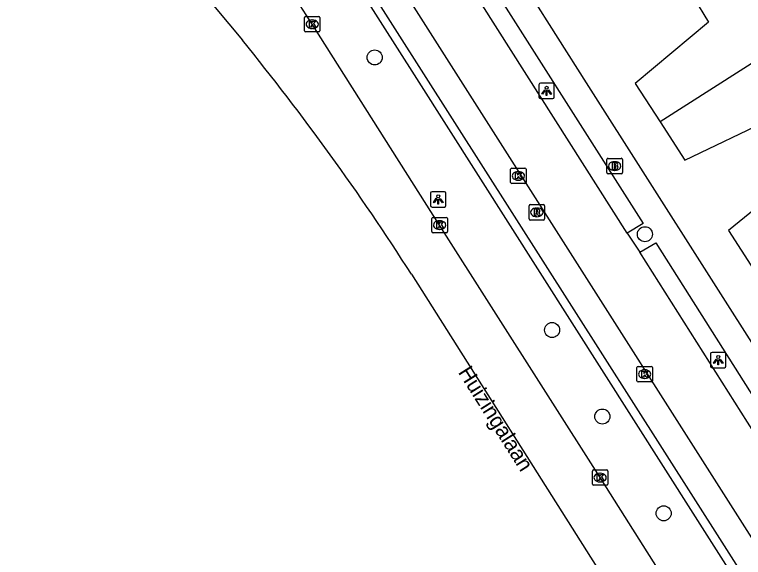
# Model space of a CAD drawing. Extents: x 159689 to 160786, y 387323 to 388339.
# Drawn here: x 159843.32 to 159890.67, y 387635.68 to 387670.93 of the extents above; entities that cross this region are included whole.
import ezdxf

# ---------------------------------------------------------------- set-up
doc = ezdxf.new("R2010")
doc.units = 0
for name, color, linetype in [('IMGEO_Boom', 7, 'Continuous'), ('IMGEO_Brandkraan', 7, 'Continuous'), ('IMGEO_Fietspad_gesloten', 7, 'Continuous'), ('IMGEO_Kolk', 7, 'Continuous'), ('IMGEO_Lichtpunt', 7, 'Continuous'), ('IMGEO_Openbare_ruimte_label', 7, 'Continuous'), ('IMGEO_OVBaan_gesloten', 7, 'Continuous'), ('IMGEO_Pand', 7, 'Continuous'), ('IMGEO_Rijbaan_regionaal_gesloten', 7, 'Continuous'), ('IMGEO_Rioolput', 7, 'Continuous'), ('IMGEO_Voetpad_open', 7, 'Continuous')]:
    doc.layers.add(name, color=color, linetype=linetype)

msp = doc.modelspace()

# ---------------------------------------------------------------- linework, layer by layer
at = {"layer": 'IMGEO_Boom'}
for centre in [(159866.716, 387668.144), (159884.273, 387656.663), (159878.24, 387650.442), (159881.507, 387644.824), (159885.49, 387638.542)]:
    msp.add_circle(centre, 0.489, dxfattribs=at)
at = {"layer": 'IMGEO_Brandkraan'}
for p, q in [((159881.807, 387660.665), (159881.807, 387661.517)), ((159881.882, 387661.591), (159882.734, 387661.591)), ((159882.295, 387661.371), (159882.32, 387661.371)), ((159882.808, 387661.517), (159882.808, 387660.665)), ((159882.734, 387660.591), (159881.882, 387660.591)), ((159882.318, 387660.811), (159882.293, 387660.811))]:
    msp.add_line(p, q, dxfattribs=at)
for points in [[(159881.807, 387660.665), (159881.807, 387661.517)], [(159881.882, 387661.591), (159882.734, 387661.591)], [(159882.808, 387661.517), (159882.808, 387660.665)], [(159882.155, 387661.291), (159882.155, 387660.891), (159882.368, 387660.891)], [(159882.386, 387661.291), (159882.155, 387661.291)], [(159882.334, 387661.21), (159882.28, 387661.21), (159882.28, 387661.134)], [(159882.28, 387661.134), (159882.333, 387661.134)], [(159882.342, 387661.058), (159882.28, 387661.058), (159882.28, 387660.977)], [(159882.28, 387660.977), (159882.342, 387660.977)], [(159882.734, 387660.591), (159881.882, 387660.591)]]:
    msp.add_lwpolyline(points, dxfattribs=at)
for centre, radius, start, end in [((159881.884, 387661.515), 0.0765, 91.552, 178.448), ((159881.884, 387661.515), 0.0765, 91.552, 178.448), ((159882.732, 387661.515), 0.0765, 1.552, 88.448), ((159882.732, 387661.515), 0.0765, 1.552, 88.448), ((159882.335, 387661.172), 0.0379, 267.8285, 90.9355), ((159882.343, 387661.017), 0.0404, 269.8759, 90.5077), ((159882.374, 387661.142), 0.251, 268.6676, 293.5347), ((159882.39, 387661.146), 0.145, 59.4692, 91.5367), ((159882.415, 387661.193), 0.0922, 285.5137, 58.1501), ((159882.42, 387661.001), 0.105, 301.3115, 78.989), ((159881.884, 387660.667), 0.0765, 181.552, 268.448), ((159881.884, 387660.667), 0.0765, 181.552, 268.448), ((159882.732, 387660.667), 0.0765, 271.552, 358.448), ((159882.732, 387660.667), 0.0765, 271.552, 358.448)]:
    msp.add_arc(centre, radius, start, end, dxfattribs=at)
for centre, major_axis, ratio, start_param, end_param in [((159882.294, 387661.091), (-0.387, 0.002), 0.722429, 4.712389, 7.853982), ((159882.319, 387661.091), (-0.39, 0.002), 0.717154, 1.570796, 4.712389)]:
    msp.add_ellipse(centre, major_axis=major_axis, ratio=ratio, start_param=start_param, end_param=end_param, dxfattribs=at)
at = {"layer": 'IMGEO_Fietspad_gesloten'}
for points in [[(159858.565, 387688.232), (159871.375, 387668.071), (159896.663, 387628.381), (159918.222, 387594.432), (159932.893, 387571.356)], [(159883.122, 387656.732), (159871.809, 387674.544)], [(159883.122, 387656.732), (159883.934, 387655.5)], [(159895.454, 387637.315), (159883.934, 387655.5)]]:
    msp.add_lwpolyline(points, dxfattribs=at)
at = {"layer": 'IMGEO_Kolk'}
for p, q in [((159862.23, 387670.801), (159863.082, 387670.801)), ((159862.155, 387669.875), (159862.155, 387670.727)), ((159862.643, 387670.581), (159862.668, 387670.581)), ((159863.156, 387670.727), (159863.156, 387669.875)), ((159862.666, 387670.021), (159862.641, 387670.021)), ((159863.082, 387669.801), (159862.23, 387669.801)), ((159875.549, 387660.026), (159875.549, 387660.878)), ((159875.624, 387660.952), (159876.476, 387660.952)), ((159876.55, 387660.878), (159876.55, 387660.026)), ((159876.037, 387660.732), (159876.062, 387660.732)), ((159876.476, 387659.952), (159875.624, 387659.952)), ((159876.06, 387660.172), (159876.035, 387660.172)), ((159870.435, 387656.833), (159870.435, 387657.685)), ((159870.51, 387657.759), (159871.362, 387657.759)), ((159870.923, 387657.539), (159870.948, 387657.539)), ((159871.436, 387657.685), (159871.436, 387656.833)), ((159871.362, 387656.759), (159870.51, 387656.759)), ((159870.946, 387656.979), (159870.921, 387656.979)), ((159883.83, 387648.078), (159884.682, 387648.078)), ((159883.755, 387647.152), (159883.755, 387648.004)), ((159884.243, 387647.858), (159884.268, 387647.858)), ((159884.756, 387648.004), (159884.756, 387647.152)), ((159884.266, 387647.298), (159884.241, 387647.298)), ((159884.682, 387647.078), (159883.83, 387647.078)), ((159880.857, 387640.436), (159880.857, 387641.288)), ((159880.932, 387641.362), (159881.784, 387641.362)), ((159881.345, 387641.142), (159881.37, 387641.142)), ((159881.858, 387641.288), (159881.858, 387640.436)), ((159881.368, 387640.582), (159881.343, 387640.582)), ((159881.784, 387640.362), (159880.932, 387640.362))]:
    msp.add_line(p, q, dxfattribs=at)
for points in [[(159862.23, 387670.801), (159863.082, 387670.801)], [(159862.155, 387669.875), (159862.155, 387670.727)], [(159862.476, 387670.501), (159862.599, 387670.501), (159862.599, 387670.35), (159862.729, 387670.501), (159862.893, 387670.501), (159862.747, 387670.35), (159862.9, 387670.101), (159862.748, 387670.101), (159862.663, 387670.265), (159862.599, 387670.198), (159862.599, 387670.101), (159862.476, 387670.101), (159862.476, 387670.501)], [(159863.156, 387670.727), (159863.156, 387669.875)], [(159863.082, 387669.801), (159862.23, 387669.801)], [(159875.549, 387660.026), (159875.549, 387660.878)], [(159875.624, 387660.952), (159876.476, 387660.952)], [(159876.55, 387660.878), (159876.55, 387660.026)], [(159875.87, 387660.652), (159875.993, 387660.652), (159875.993, 387660.501), (159876.123, 387660.652), (159876.287, 387660.652), (159876.141, 387660.501), (159876.294, 387660.252), (159876.142, 387660.252), (159876.057, 387660.416), (159875.993, 387660.349), (159875.993, 387660.252), (159875.87, 387660.252), (159875.87, 387660.652)], [(159876.476, 387659.952), (159875.624, 387659.952)], [(159870.435, 387656.833), (159870.435, 387657.685)], [(159870.51, 387657.759), (159871.362, 387657.759)], [(159871.436, 387657.685), (159871.436, 387656.833)], [(159870.756, 387657.459), (159870.879, 387657.459), (159870.879, 387657.308), (159871.009, 387657.459), (159871.173, 387657.459), (159871.027, 387657.308), (159871.18, 387657.059), (159871.028, 387657.059), (159870.943, 387657.223), (159870.879, 387657.156), (159870.879, 387657.059), (159870.756, 387657.059), (159870.756, 387657.459)], [(159871.362, 387656.759), (159870.51, 387656.759)], [(159883.83, 387648.078), (159884.682, 387648.078)], [(159883.755, 387647.152), (159883.755, 387648.004)], [(159884.076, 387647.778), (159884.199, 387647.778), (159884.199, 387647.627), (159884.329, 387647.778), (159884.493, 387647.778), (159884.347, 387647.627), (159884.5, 387647.378), (159884.348, 387647.378), (159884.263, 387647.542), (159884.199, 387647.475), (159884.199, 387647.378), (159884.076, 387647.378), (159884.076, 387647.778)], [(159884.756, 387648.004), (159884.756, 387647.152)], [(159884.682, 387647.078), (159883.83, 387647.078)], [(159880.857, 387640.436), (159880.857, 387641.288)], [(159880.932, 387641.362), (159881.784, 387641.362)], [(159881.178, 387641.062), (159881.301, 387641.062), (159881.301, 387640.911), (159881.431, 387641.062), (159881.595, 387641.062), (159881.449, 387640.911), (159881.602, 387640.662), (159881.45, 387640.662), (159881.365, 387640.826), (159881.301, 387640.759), (159881.301, 387640.662), (159881.178, 387640.662), (159881.178, 387641.062)], [(159881.858, 387641.288), (159881.858, 387640.436)], [(159881.784, 387640.362), (159880.932, 387640.362)]]:
    msp.add_lwpolyline(points, dxfattribs=at)
for centre, start, end in [((159862.232, 387670.725), 91.552, 178.448), ((159862.232, 387670.725), 91.552, 178.448), ((159863.08, 387670.725), 1.552, 88.448), ((159863.08, 387670.725), 1.552, 88.448), ((159862.232, 387669.877), 181.552, 268.448), ((159862.232, 387669.877), 181.552, 268.448), ((159863.08, 387669.877), 271.552, 358.448), ((159863.08, 387669.877), 271.552, 358.448), ((159875.626, 387660.876), 91.552, 178.448), ((159875.626, 387660.876), 91.552, 178.448), ((159876.474, 387660.876), 1.552, 88.448), ((159876.474, 387660.876), 1.552, 88.448), ((159875.626, 387660.028), 181.552, 268.448), ((159875.626, 387660.028), 181.552, 268.448), ((159876.474, 387660.028), 271.552, 358.448), ((159876.474, 387660.028), 271.552, 358.448), ((159870.512, 387657.683), 91.552, 178.448), ((159870.512, 387657.683), 91.552, 178.448), ((159871.36, 387657.683), 1.552, 88.448), ((159871.36, 387657.683), 1.552, 88.448), ((159870.512, 387656.835), 181.552, 268.448), ((159870.512, 387656.835), 181.552, 268.448), ((159871.36, 387656.835), 271.552, 358.448), ((159871.36, 387656.835), 271.552, 358.448), ((159883.832, 387648.002), 91.552, 178.448), ((159883.832, 387648.002), 91.552, 178.448), ((159884.68, 387648.002), 1.552, 88.448), ((159884.68, 387648.002), 1.552, 88.448), ((159883.832, 387647.154), 181.552, 268.448), ((159883.832, 387647.154), 181.552, 268.448), ((159884.68, 387647.154), 271.552, 358.448), ((159884.68, 387647.154), 271.552, 358.448), ((159880.934, 387641.286), 91.552, 178.448), ((159880.934, 387641.286), 91.552, 178.448), ((159881.782, 387641.286), 1.552, 88.448), ((159881.782, 387641.286), 1.552, 88.448), ((159880.934, 387640.438), 181.552, 268.448), ((159880.934, 387640.438), 181.552, 268.448), ((159881.782, 387640.438), 271.552, 358.448), ((159881.782, 387640.438), 271.552, 358.448)]:
    msp.add_arc(centre, 0.0765, start, end, dxfattribs=at)
for centre, major_axis, ratio, start_param, end_param in [((159862.642, 387670.301), (-0.387, 0.002), 0.722429, 4.712389, 7.853982), ((159862.667, 387670.301), (-0.39, 0.002), 0.717154, 1.570796, 4.712389), ((159876.036, 387660.452), (-0.387, 0.002), 0.722429, 4.712389, 7.853982), ((159876.061, 387660.452), (-0.39, 0.002), 0.717154, 1.570796, 4.712389), ((159870.922, 387657.259), (-0.387, 0.002), 0.722429, 4.712389, 7.853982), ((159870.947, 387657.259), (-0.39, 0.002), 0.717154, 1.570796, 4.712389), ((159884.242, 387647.578), (-0.387, 0.002), 0.722429, 4.712389, 7.853982), ((159884.267, 387647.578), (-0.39, 0.002), 0.717154, 1.570796, 4.712389), ((159881.344, 387640.862), (-0.387, 0.002), 0.722429, 4.712389, 7.853982), ((159881.369, 387640.862), (-0.39, 0.002), 0.717154, 1.570796, 4.712389)]:
    msp.add_ellipse(centre, major_axis=major_axis, ratio=ratio, start_param=start_param, end_param=end_param, dxfattribs=at)
at = {"layer": 'IMGEO_Lichtpunt'}
for p, q in [((159877.386, 387666.373), (159877.386, 387665.566)), ((159877.386, 387666.373), (159877.386, 387665.566)), ((159878.288, 387666.468), (159877.48, 387666.468)), ((159878.288, 387666.468), (159877.48, 387666.468)), ((159878.382, 387665.566), (159878.382, 387666.373)), ((159878.382, 387665.566), (159878.382, 387666.373)), ((159877.48, 387665.472), (159878.288, 387665.472)), ((159877.48, 387665.472), (159878.288, 387665.472)), ((159870.346, 387659.33), (159870.346, 387658.523)), ((159870.346, 387659.33), (159870.346, 387658.523)), ((159871.248, 387659.425), (159870.44, 387659.425)), ((159871.248, 387659.425), (159870.44, 387659.425)), ((159871.342, 387658.523), (159871.342, 387659.33)), ((159871.342, 387658.523), (159871.342, 387659.33)), ((159870.44, 387658.429), (159871.248, 387658.429)), ((159870.44, 387658.429), (159871.248, 387658.429)), ((159888.536, 387648.897), (159888.536, 387648.09)), ((159888.536, 387648.897), (159888.536, 387648.09)), ((159889.438, 387648.992), (159888.63, 387648.992)), ((159889.438, 387648.992), (159888.63, 387648.992)), ((159889.532, 387648.09), (159889.532, 387648.897)), ((159889.532, 387648.09), (159889.532, 387648.897)), ((159888.63, 387647.996), (159889.438, 387647.996)), ((159888.63, 387647.996), (159889.438, 387647.996))]:
    msp.add_line(p, q, dxfattribs=at)
for points in [[(159877.76, 387666.037), (159877.799, 387666.009), (159877.611, 387665.747), (159877.573, 387665.774), (159877.76, 387666.037)], [(159877.862, 387665.989), (159877.909, 387665.989), (159877.909, 387665.667), (159877.862, 387665.667), (159877.862, 387665.989)], [(159877.972, 387666.009), (159878.01, 387666.036), (159878.197, 387665.774), (159878.158, 387665.746), (159877.972, 387666.009)], [(159870.72, 387658.994), (159870.759, 387658.966), (159870.571, 387658.704), (159870.533, 387658.731), (159870.72, 387658.994)], [(159870.932, 387658.966), (159870.97, 387658.993), (159871.157, 387658.731), (159871.118, 387658.703), (159870.932, 387658.966)], [(159870.822, 387658.946), (159870.869, 387658.946), (159870.869, 387658.624), (159870.822, 387658.624), (159870.822, 387658.946)], [(159888.91, 387648.561), (159888.949, 387648.533), (159888.761, 387648.271), (159888.723, 387648.298), (159888.91, 387648.561)], [(159889.122, 387648.533), (159889.16, 387648.56), (159889.347, 387648.298), (159889.308, 387648.27), (159889.122, 387648.533)], [(159889.012, 387648.513), (159889.059, 387648.513), (159889.059, 387648.191), (159889.012, 387648.191), (159889.012, 387648.513)]]:
    msp.add_lwpolyline(points, dxfattribs=at)
for centre in [(159877.885, 387666.171), (159870.845, 387659.128), (159889.035, 387648.695)]:
    msp.add_circle(centre, 0.0994, dxfattribs=at)
for centre, start, end in [((159877.48, 387666.373), 90, 180), ((159877.48, 387666.373), 90, 180), ((159878.288, 387666.373), 0, 90), ((159878.288, 387666.373), 0, 90), ((159877.48, 387665.566), 180, 270), ((159877.48, 387665.566), 180, 270), ((159878.288, 387665.566), 270, 0), ((159878.288, 387665.566), 270, 360), ((159870.44, 387659.33), 90, 180), ((159870.44, 387659.33), 90, 180), ((159871.248, 387659.33), 0, 90), ((159871.248, 387659.33), 0, 90), ((159870.44, 387658.523), 180, 270), ((159870.44, 387658.523), 180, 270), ((159871.248, 387658.523), 270, 0), ((159871.248, 387658.523), 270, 360), ((159888.63, 387648.897), 90, 180), ((159888.63, 387648.897), 90, 180), ((159889.438, 387648.897), 0, 90), ((159889.438, 387648.897), 0, 90), ((159888.63, 387648.09), 180, 270), ((159888.63, 387648.09), 180, 270), ((159889.438, 387648.09), 270, 0), ((159889.438, 387648.09), 270, 360)]:
    msp.add_arc(centre, 0.0946, start, end, dxfattribs=at)
at = {"layer": 'IMGEO_OVBaan_gesloten'}
for points in [[(159855.36, 387672.605), (159858.121, 387669.257)], [(159869.099, 387654.066), (159900.012, 387605.234)]]:
    msp.add_lwpolyline(points, dxfattribs=at)
msp.add_arc((159732.596, 387566.983), 161.915, 32.53631, 39.17231, dxfattribs=at)
at = {"layer": 'IMGEO_Pand'}
for points in [[(159900.864, 387673.918), (159885.255, 387663.953)], [(159887.426, 387672.056), (159888.398, 387670.432), (159883.636, 387666.456), (159885.255, 387663.953)], [(159885.255, 387663.953), (159886.863, 387661.467), (159892.467, 387664.154), (159893.533, 387662.473)], [(159893.533, 387662.473), (159894.563, 387660.849), (159889.712, 387656.9), (159891.343, 387654.352)]]:
    msp.add_lwpolyline(points, dxfattribs=at)
at = {"layer": 'IMGEO_Rijbaan_regionaal_gesloten'}
msp.add_lwpolyline([(159895.607, 387618.335), (159893.876, 387621.079), (159881.358, 387640.862), (159870.936, 387657.259), (159862.656, 387670.301), (159859.345, 387675.48), (159854.91, 387682.508), (159848.808, 387692.139), (159844.283, 387699.312), (159843.801, 387700.086), (159843.321, 387700.86)], dxfattribs=at)
at = {"layer": 'IMGEO_Rioolput'}
for p, q in [((159876.749, 387657.657), (159876.749, 387658.509)), ((159876.824, 387658.583), (159877.676, 387658.583)), ((159877.75, 387658.509), (159877.75, 387657.657)), ((159877.237, 387658.363), (159877.262, 387658.363)), ((159877.676, 387657.583), (159876.824, 387657.583)), ((159877.26, 387657.803), (159877.235, 387657.803))]:
    msp.add_line(p, q, dxfattribs=at)
for points in [[(159876.749, 387657.657), (159876.749, 387658.509)], [(159876.824, 387658.583), (159877.676, 387658.583)], [(159877.75, 387658.509), (159877.75, 387657.657)], [(159877.338, 387658.281), (159877.086, 387658.283), (159877.086, 387657.883)], [(159877.086, 387657.883), (159877.21, 387657.883), (159877.21, 387658.045), (159877.221, 387658.045)], [(159877.264, 387658.202), (159877.21, 387658.202), (159877.21, 387658.121)], [(159877.21, 387658.121), (159877.262, 387658.121)], [(159877.268, 387658.016), (159877.339, 387657.883), (159877.479, 387657.883), (159877.414, 387658.009)], [(159877.676, 387657.583), (159876.824, 387657.583)]]:
    msp.add_lwpolyline(points, dxfattribs=at)
for centre, radius, start, end in [((159876.826, 387658.507), 0.0765, 91.552, 178.448), ((159876.826, 387658.507), 0.0765, 91.552, 178.448), ((159877.674, 387658.507), 0.0765, 1.552, 88.448), ((159877.674, 387658.507), 0.0765, 1.552, 88.448), ((159877.22, 387657.992), 0.0533, 26.0293, 88.6989), ((159877.246, 387658.31), 0.19, 274.7715, 282.9687), ((159877.27, 387658.106), 0.0964, 77.0061, 93.1865), ((159877.284, 387658.163), 0.0378, 276.6634, 79.6772), ((159877.337, 387658.171), 0.109, 350.3612, 89.416), ((159877.335, 387658.171), 0.112, 277.5842, 350.9817), ((159877.319, 387657.956), 0.108, 29.5134, 73.7905), ((159876.826, 387657.659), 0.0765, 181.552, 268.448), ((159876.826, 387657.659), 0.0765, 181.552, 268.448), ((159877.674, 387657.659), 0.0765, 271.552, 358.448), ((159877.674, 387657.659), 0.0765, 271.552, 358.448)]:
    msp.add_arc(centre, radius, start, end, dxfattribs=at)
for centre, major_axis, ratio, start_param, end_param in [((159877.236, 387658.083), (-0.387, 0.002), 0.722429, 4.712389, 7.853982), ((159877.261, 387658.083), (-0.39, 0.002), 0.717154, 1.570796, 4.712389)]:
    msp.add_ellipse(centre, major_axis=major_axis, ratio=ratio, start_param=start_param, end_param=end_param, dxfattribs=at)
at = {"layer": 'IMGEO_Voetpad_open'}
for points in [[(159925.947, 387595.016), (159925.086, 387596.373), (159913.458, 387614.655), (159903.748, 387629.93), (159892.284, 387647.962), (159880.486, 387666.503), (159871.272, 387681.013), (159866.365, 387688.698), (159861.884, 387695.822), (159856.385, 387704.612), (159855.275, 387706.413), (159852.398, 387711.107)], [(159930.011, 387572.581), (159916.611, 387593.674), (159895.175, 387627.432), (159869.914, 387667.073), (159857.025, 387687.322), (159856.897, 387687.521), (159856.768, 387687.721)], [(159915.314, 387592.825), (159916.154, 387593.379), (159913.887, 387596.942), (159902.311, 387615.135), (159894.697, 387627.102), (159893.433, 387629.088), (159887.557, 387638.32), (159869.453, 387666.765), (159856.552, 387687.024), (159856.448, 387687.183), (159856.345, 387687.342)], [(159871.809, 387674.544), (159872.831, 387675.167), (159884.166, 387657.358), (159883.122, 387656.732)], [(159883.934, 387655.5), (159884.972, 387656.109), (159896.483, 387637.94), (159895.454, 387637.315)]]:
    msp.add_lwpolyline(points, dxfattribs=at)

# ---------------------------------------------------------------- texts
at = {"layer": 'IMGEO_Openbare_ruimte_label'}
msp.add_text('Huizingalaan', height=1, rotation=302.2909, dxfattribs=at).set_placement((159872.106, 387647.701))

doc.saveas('drawing.dxf')
